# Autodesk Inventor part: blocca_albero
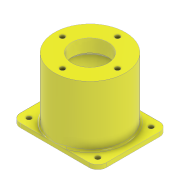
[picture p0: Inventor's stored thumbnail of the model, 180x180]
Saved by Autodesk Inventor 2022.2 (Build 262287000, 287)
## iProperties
Created: 2025-03
Part Number: blocca_albero
Material: Generico
Document SubType Name: Modeling
Designer: 18907419
Density: 1 g/cm^3
Appearance: Giallo
Author: 18907419
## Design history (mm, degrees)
sketch "Schizzo1"
  geometry: L1 (-14.125, 150)-(14.125, 150) reference; L2 (14.125, 110)-(-14.125, 110) reference; L3 (0, 150)-(0, 110); L4 (21, 150)-(21, 162) reference; L5 (21, 110)-(21, 98) reference; L6 (20.925, 150)-(21, 150); L7 (21, 165.089)-(41, 165.089); L8 (0, 130)-(46.101, 130); L9 (41, 165.089)-(41, 130); L10 (21, 110)-(21, 98); L11 (20.925, 110)-(21, 110); L12 (21, 94.911)-(41, 94.911); L13 (41, 94.911)-(41, 130); L14 (21, 165.089)-(21, 94.911); L15 (20.925, 110)-(25.925, 110); L16 (25.925, 110)-(25.925, 130); L17 (21, 150)-(25.925, 150); L18 (25.925, 150)-(25.925, 130); 4 further points
  constraints: 32 end point, 6 point on line, 3 midpoint, 3 symmetric about line, 2 vertical, 4 other
  dimensions: "d0" = 20 distance of L7.start L7.end; "d2" = 5 distance of L11.start L15.end
revolve "Rivoluzione1" sketch "Schizzo1" stored, may be unused: angle "d1" = 360 deg
sketch "Schizzo2"
  geometry: C1 r 41 at (0, 0) reference; C2 r 21 at (0, 0); 1 further point
  constraints: 1 centre point, 1 coincident
  dimensions: "d3" = 42 diameter of C2
extrude "Estrusione1" join sketch "Schizzo2" distance "d4" = 5; taper "d5" = 0 deg
sketch "Schizzo3"
  geometry: L1 (0, 41)-(50, 41); L2 (50, 41)-(50, -6); L3 (0, -41)-(50, -41); L4 (50, -41)-(50, -6); L5 (0, 0)-(0, 41); L6 (0, 41)-(-50, 41); L7 (-50, 41)-(-50, -6); L8 (-50, -41)-(-50, -6); L9 (0, -41)-(-50, -41); C1 r 21 at (0, 0) reference; A1 r 41 centre (0, 0) between (0, 41) and (0, -41) reference; 1 further point
  constraints: 18 end point, 3 perpendicular, 3 symmetric about line, 2 point on circle
  dimensions: "d6" = 50 distance of L1.start L1.end
extrude "Estrusione2" join sketch "Schizzo3" distance "d7" = 5; taper "d8" = 0 deg
fillet "Raccordo1" dims "d9" = 10
sketch "Schizzo5"
  geometry: 17 further points
  constraints: 4 coincident, 4 other
hole "Foro1" sketch "Schizzo5" at (-40, -31), (40, -31), (40, 31), (-40, 31) diameter "d10" = 5.5; stored, may be unused: countersink angle "d14" = 90 deg, drill point angle "d16" = 118 deg; dims "d11" = 6, "d12" = 10.4, "d13" = 2, "d15" = 8
chamfer "Smusso1" distance "d17" = 2; stored, may be unused: second distance "d18" = 2, angle "d19" = 45 deg
fillet "Raccordo2" dims "d20" = 2
sketch "Schizzo6"
  geometry: C1 r 1.6 at (32, 0) reference; 1 further point
hole "Foro2" sketch "Schizzo6" at (32, 0) diameter "d21" = 5.5; stored, may be unused: countersink angle "d25" = 90 deg, drill point angle "d27" = 118 deg; dims "d22" = 6, "d23" = 11, "d24" = 2.6, "d26" = 8
pattern_circular "Serie circolare1" dims angle "d29" = 360 deg
chamfer "Smusso2" distance "d31" = 4.9; stored, may be unused: second distance "d32" = 2, angle "d33" = 45 deg
node "Solido1"
node "Riferimento1"
node "Riferimento2"
node "Riferimento3"
